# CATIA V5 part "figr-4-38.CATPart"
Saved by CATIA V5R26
Part number: Part1
Bounding box of the stored display mesh (mm): x 0 to 127.525, y -106.271 to 100, z 0 to 100
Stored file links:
  D:\_Deepak\CATIA\CATIA V5-6R2016_Deepak\Resources\Part files\Partfiles\c04_catia_v5_6r2016_prt\figr-4-38.CATPart
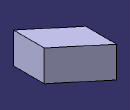
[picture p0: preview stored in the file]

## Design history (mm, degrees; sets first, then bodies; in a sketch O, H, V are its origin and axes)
Body1 (main body)
  Sketch1 on yz-plane, origin (0, 0, 0), H (0, 1, 0), V (0, 0, 1)
    line L1 (0, 0) -> (100, 0)
    line L2 (100, 0) -> (100, 100)
    line L3 (100, 100) -> (0, 100)
    line L4 (0, 100) -> (0, 0)
    horizontal: L1 H, L3 H
    vertical: L2 V, L4 V
  Sketch2 on xy-plane, origin (0, 0, 0), H (1, 0, 0), V (0, 1, 0)
    line L1 (0, 0) -> (60, -50)
  Pad1: profile Sketch1, direction along edge of Sketch2, length 166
